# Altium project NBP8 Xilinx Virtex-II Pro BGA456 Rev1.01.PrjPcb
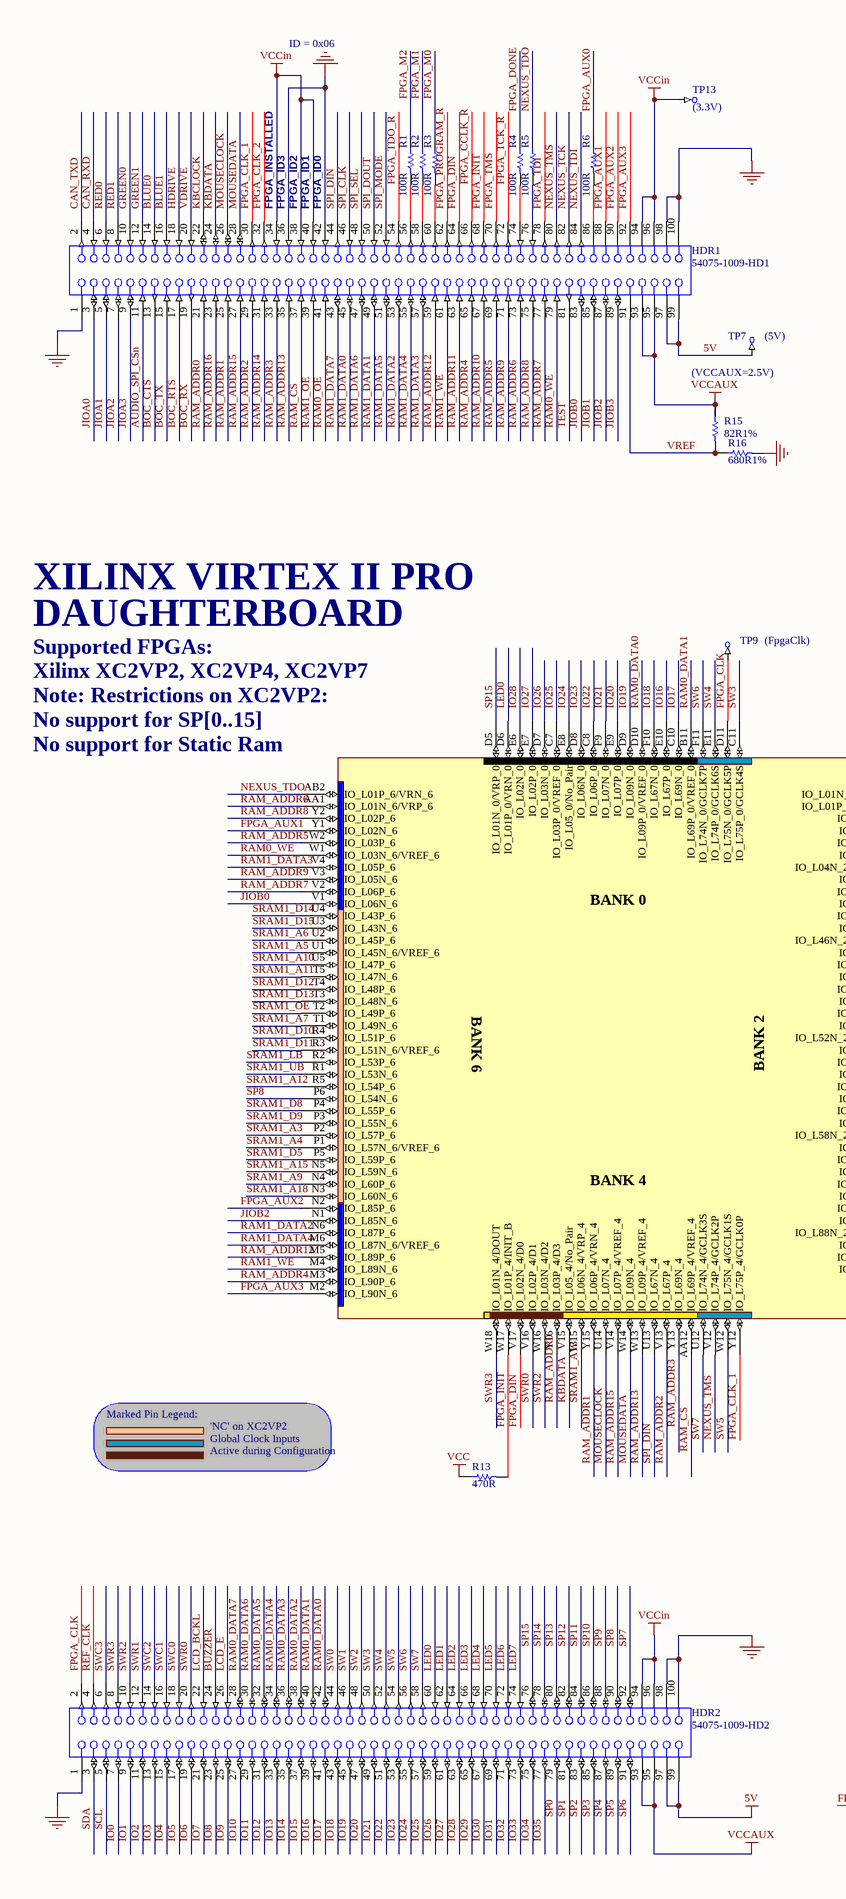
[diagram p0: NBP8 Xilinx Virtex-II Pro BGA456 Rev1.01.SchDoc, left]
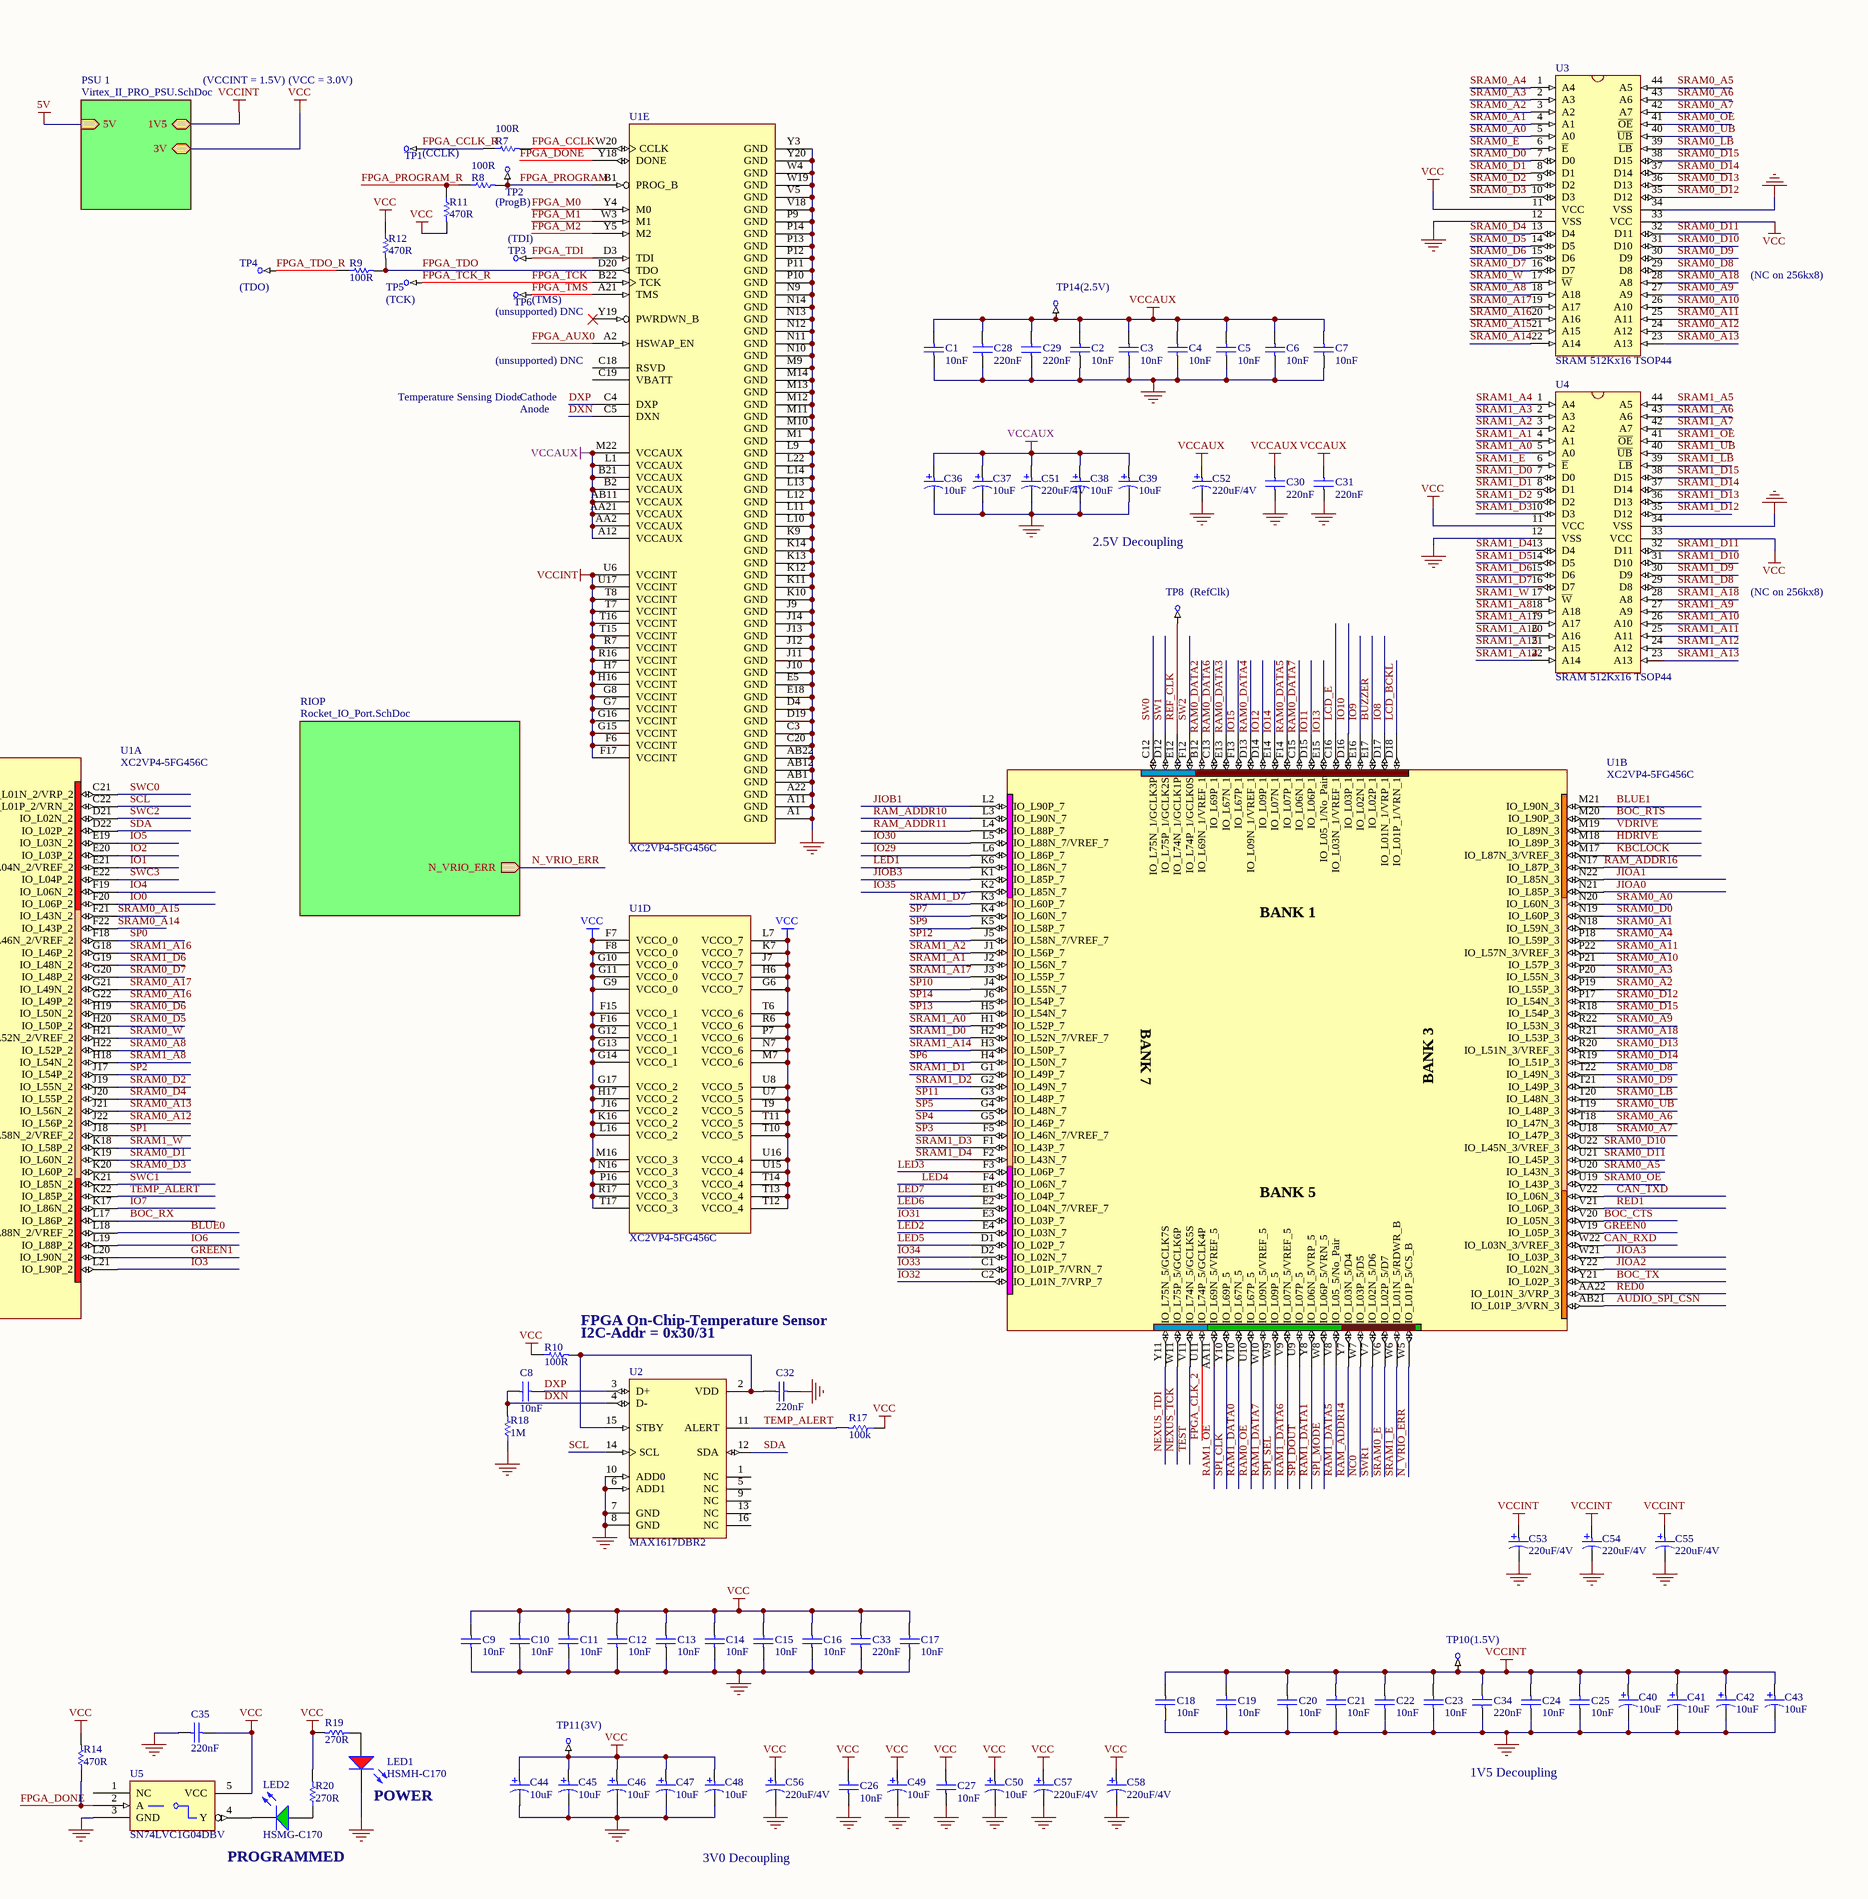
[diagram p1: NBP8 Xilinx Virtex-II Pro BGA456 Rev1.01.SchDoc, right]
3 sheets, 164 parts. Net scope: hierarchical (ports join the sheet entries above them; power ports are global).
Board file: NBP8 Xilinx Virtex-II Pro BGA456 Rev1.01.PcbDoc
Sheets:
  NBP8 Xilinx Virtex-II Pro BGA456 Rev1.01.SchDoc
    PSU 1 = Virtex_II_PRO_PSU.SchDoc
    RIOP = Rocket_IO_Port.SchDoc

## Sheet NBP8 Xilinx Virtex-II Pro BGA456 Rev1.01.SchDoc
size A2; Organization: Altium Limited; Address1: L3, 12a Rodborough Rd; Address2: Frenchs Forest; Address3: NSW; Address4: Australia 2086; DocumentNumber: 3; Revision: 1.01; SheetNumber: 3; SheetTotal: 3

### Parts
C1  10nF  [CC1608-0603]
C2  10nF  [CC1608-0603]
C3  10nF  [CC1608-0603]
C4  10nF  [CC1608-0603]
C5  10nF  [CC1608-0603]
C6  10nF  [CC1608-0603]
C7  10nF  [CC1608-0603]
C8  10nF  [CC1608-0603]
C9  10nF  [CC1608-0603]
C10  10nF  [CC1608-0603]
C11  10nF  [CC1608-0603]
C12  10nF  [CC1608-0603]
C13  10nF  [CC1608-0603]
C14  10nF  [CC1608-0603]
C15  10nF  [CC1608-0603]
C16  10nF  [CC1608-0603]
C17  10nF  [CC1608-0603]
C18  10nF  [CC1608-0603]
C19  10nF  [CC1608-0603]
C20  10nF  [CC1608-0603]
C21  10nF  [CC1608-0603]
C22  10nF  [CC1608-0603]
C23  10nF  [CC1608-0603]
C24  10nF  [CC1608-0603]
C25  10nF  [CC1608-0603]
C26  10nF  [CC1608-0603]
C27  10nF  [CC1608-0603]
C28  220nF  [CC1608-0603]
C29  220nF  [CC1608-0603]
C30  220nF  [CC1608-0603]
C31  220nF  [CC1608-0603]
C32  220nF  [CC1608-0603]
C33  220nF  [CC1608-0603]
C34  220nF  [CC1608-0603]
C35  220nF  [CC1608-0603]
C36  10uF  [MCCT-B]
C37  10uF  [MCCT-B]
C38  10uF  [MCCT-B]
C39  10uF  [MCCT-B]
C40  10uF  [MCCT-B]
C41  10uF  [MCCT-B]
C42  10uF  [MCCT-B]
C43  10uF  [MCCT-B]
C44  10uF  [MCCT-B]
C45  10uF  [MCCT-B]
C46  10uF  [MCCT-B]
C47  10uF  [MCCT-B]
C48  10uF  [MCCT-B]
C49  10uF  [MCCT-B]
C50  10uF  [MCCT-B]
C51  220uF/4V  [MCCT-D]
C52  220uF/4V  [MCCT-D]
C53  220uF/4V  [MCCT-D]
C54  220uF/4V  [MCCT-D]
C55  220uF/4V  [MCCT-D]
C56  220uF/4V  [MCCT-D]
C57  220uF/4V  [MCCT-D]
C58  220uF/4V  [MCCT-D]
HDR1  54075-1009-HD1  [54075]
HDR2  54075-1009-HD2  [54075]
LED1  HSMH-C170  [SMD _LED]
LED2  HSMG-C170  [SMD _LED]
R1  100R  [CC2012-0805]
R2  100R  [CC2012-0805]
R3  100R  [CC2012-0805]
R4  100R  [CC2012-0805]
R5  100R  [CC2012-0805]
R6  100R  [CC2012-0805]
R7  100R  [CC2012-0805]
R8  100R  [CC2012-0805]
R9  100R  [CC2012-0805]
R10  100R  [CC2012-0805]
R11  470R  [CC2012-0805]
R12  470R  [CC2012-0805]
R13  470R  [CC2012-0805]
R14  470R  [CC2012-0805]
R15  82R1%  [CC2012-0805]
R16  680R1%  [CC2012-0805]
R17  100k  [CC2012-0805]
R18  1M  [CC2012-0805]
R19  270R  [CC2012-0805]
R20  270R  [CC2012-0805]
TP1  (CCLK)  [TestPin]  (no BOM)
TP2  (ProgB)  [TestPin]  (no BOM)
TP3  (TDI)  [TestPin]  (no BOM)
TP4  (TDO)  [TestPin]  (no BOM)
TP5  (TCK)  [TestPin]  (no BOM)
TP6  (TMS)  [TestPin]  (no BOM)
TP7  (5V)  [TestPin]  (no BOM)
TP8  (RefClk)  [TestPin]  (no BOM)
TP9  (FpgaClk)  [TestPin]  (no BOM)
TP10  (1.5V)  [TestPin]  (no BOM)
TP11  (3V)  [TestPin]  (no BOM)
TP13  (3.3V)  [TestPin]  (no BOM)
TP14  (2.5V)  [TestPin]  (no BOM)
U1  XC2VP4-5FG456C  [FG456]  (parts A,B,D,E of 5)
U2  MAX1617DBR2  [QSOP16]
U3  SRAM 512Kx16 TSOP44  [SO-G44/P.8]
U4  SRAM 512Kx16 TSOP44  [SO-G44/P.8]
U5  SN74LVC1G04DBV  [SO-G5/P.95]

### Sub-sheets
PSU 1 = Virtex_II_PRO_PSU.SchDoc: 5V (in), 1V5, 3V
RIOP = Rocket_IO_Port.SchDoc: N_VRIO_ERR (out)

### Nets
5V: HDR1.97 HDR1.99 HDR2.97 HDR2.99 TP7.1 ; sheet PSU 1/5V
GND: C1.2 C2.2 C3.2 C4.2 C5.2 C6.2 C7.2 C9.2 C10.2 C11.2 C12.2 C13.2 C14.2 C15.2 C16.2 C17.2 C18.2 C19.2 C20.2 C21.2 C22.2 C23.2 C24.2 C25.2 C26.2 C27.2 C28.2 C29.2 C30.2 C31.2 C32.1 C33.2 C34.2 C35.2 C36.2 C37.2 C38.2 C39.2 C40.2 C41.2 C42.2 C43.2 C44.2 C45.2 C46.2 C47.2 C48.2 C49.2 C50.2 C51.2 C52.2 C53.2 C54.2 C55.2 C56.2 C57.2 C58.2 HDR1.1 HDR1.36 HDR1.42 HDR1.98 HDR1.100 HDR2.1 HDR2.98 HDR2.100 LED1.2(K) R16.2 R18.1 U1.A1(GND) U1.A11(GND) U1.A22(GND) U1.AB1(GND) U1.AB12(GND) U1.AB22(GND) U1.C3(GND) U1.C20(GND) U1.D4(GND) U1.D19(GND) U1.E5(GND) U1.E18(GND) U1.J9(GND) U1.J10(GND) U1.J11(GND) U1.J12(GND) U1.J13(GND) U1.J14(GND) U1.K9(GND) U1.K10(GND) U1.K11(GND) U1.K12(GND) U1.K13(GND) U1.K14(GND) U1.L9(GND) U1.L10(GND) U1.L11(GND) U1.L12(GND) U1.L13(GND) U1.L14(GND) U1.L22(GND) U1.M1(GND) U1.M9(GND) U1.M10(GND) U1.M11(GND) U1.M12(GND) U1.M13(GND) U1.M14(GND) U1.N9(GND) U1.N10(GND) U1.N11(GND) U1.N12(GND) U1.N13(GND) U1.N14(GND) U1.P9(GND) U1.P10(GND) U1.P11(GND) U1.P12(GND) U1.P13(GND) U1.P14(GND) U1.V5(GND) U1.V18(GND) U1.W4(GND) U1.W19(GND) U1.Y3(GND) U1.Y20(GND) U2.6(ADD1) U2.7(GND) U2.8(GND) U2.10(ADD0) U3.12(VSS) U3.34(VSS) U4.12(VSS) U4.34(VSS) U5.3(GND)
VCC: C9.1 C10.1 C11.1 C12.1 C13.1 C14.1 C15.1 C16.1 C17.1 C26.1 C27.1 C33.1 C35.1 C44.1 C45.1 C46.1 C47.1 C48.1 C49.1 C50.1 C56.1 C57.1 C58.1 R10.1 R11.2 R12.1 R13.1 R14.2 R17.1 R19.2 R20.2 TP11.1 U1.F7(VCCO_0) U1.F8(VCCO_0) U1.F15(VCCO_1) U1.F16(VCCO_1) U1.G6(VCCO_7) U1.G9(VCCO_0) U1.G10(VCCO_0) U1.G11(VCCO_0) U1.G12(VCCO_1) U1.G13(VCCO_1) U1.G14(VCCO_1) U1.G17(VCCO_2) U1.H6(VCCO_7) U1.H17(VCCO_2) U1.J7(VCCO_7) U1.J16(VCCO_2) U1.K7(VCCO_7) U1.K16(VCCO_2) U1.L7(VCCO_7) U1.L16(VCCO_2) U1.M7(VCCO_6) U1.M16(VCCO_3) U1.N7(VCCO_6) U1.N16(VCCO_3) U1.P7(VCCO_6) U1.P16(VCCO_3) U1.R6(VCCO_6) U1.R17(VCCO_3) U1.T6(VCCO_6) U1.T9(VCCO_5) U1.T10(VCCO_5) U1.T11(VCCO_5) U1.T12(VCCO_4) U1.T13(VCCO_4) U1.T14(VCCO_4) U1.T17(VCCO_3) U1.U7(VCCO_5) U1.U8(VCCO_5) U1.U15(VCCO_4) U1.U16(VCCO_4) U3.11(VCC) U3.33(VCC) U4.11(VCC) U4.33(VCC) U5.5(VCC) ; sheet PSU 1/3V
VCCAUX: C1.1 C2.1 C3.1 C4.1 C5.1 C6.1 C7.1 C28.1 C29.1 C30.1 C31.1 C36.1 C37.1 C38.1 C39.1 C51.1 C52.1 HDR1.93 HDR1.95 HDR2.93 HDR2.95 R15.1 TP14.1 U1.A12(VCCAUX) U1.AA2(VCCAUX) U1.AA21(VCCAUX) U1.AB11(VCCAUX) U1.B2(VCCAUX) U1.B21(VCCAUX) U1.L1(VCCAUX) U1.M22(VCCAUX)
VCCin: HDR1.34 HDR1.38 HDR1.40 HDR1.94 HDR1.96 HDR2.94 HDR2.96 TP13.1
VCCINT: C18.1 C19.1 C20.1 C21.1 C22.1 C23.1 C24.1 C25.1 C34.1 C40.1 C41.1 C42.1 C43.1 C53.1 C54.1 C55.1 TP10.1 U1.F6(VCCINT) U1.F17(VCCINT) U1.G7(VCCINT) U1.G8(VCCINT) U1.G15(VCCINT) U1.G16(VCCINT) U1.H7(VCCINT) U1.H16(VCCINT) U1.R7(VCCINT) U1.R16(VCCINT) U1.T7(VCCINT) U1.T8(VCCINT) U1.T15(VCCINT) U1.T16(VCCINT) U1.U6(VCCINT) U1.U17(VCCINT) ; sheet PSU 1/1V5
AUDIO_SPI_CSn: HDR1.11 U1.AB21(IO_L01P_3/VRN_3)
BLUE0: HDR1.14 U1.L18(IO_L88N_2/VREF_2)
BLUE1: HDR1.16 U1.M21(IO_L90N_3)
BOC_CTS: HDR1.13 U1.V20(IO_L05N_3)
BOC_RTS: HDR1.17 U1.M20(IO_L90P_3)
BOC_RX: HDR1.19 U1.L17(IO_L86P_2)
BOC_TX: HDR1.15 U1.Y21(IO_L02P_3)
BUZZER: HDR2.24 U1.E17(IO_L02P_1)
CAN_RXD: HDR1.4 U1.W22(IO_L03N_3/VREF_3)
CAN_TXD: HDR1.2 U1.V22(IO_L06N_3)
DXN: C8.1 R18.2 U1.C5(DXN) U2.4(D-)
DXP: C8.2 U1.C4(DXP) U2.3(D+)
FPGA_AUX0: R6.1 U1.A2(HSWAP_EN)
FPGA_AUX1: HDR1.88 U1.Y1(IO_L02N_6)
FPGA_AUX2: HDR1.90 U1.N2(IO_L85P_6)
FPGA_AUX3: HDR1.92 U1.M2(IO_L90N_6)
FPGA_CCLK: R7.2 U1.W20(CCLK)
FPGA_CCLK_R: HDR1.66 R7.1 TP1.1
FPGA_CLK: HDR2.2 TP9.1 U1.D11(IO_L75N_0/GCLK5P)
FPGA_CLK_1: HDR1.30 U1.Y12(IO_L75P_4/GCLK0P)
FPGA_CLK_2: HDR1.32 U1.U11(IO_L74P_5/GCLK4P)
FPGA_DIN: HDR1.64 U1.V17(IO_L02N_4/D0)
FPGA_DONE: R4.1 R14.1 U1.Y18(DONE) U5.2(A)
FPGA_INIT: HDR1.68 R13.2 U1.W17(IO_L01P_4/INIT_B)
FPGA_M0: R3.1 U1.Y4(M0)
FPGA_M1: R2.1 U1.W3(M1)
FPGA_M2: R1.1 U1.Y5(M2)
FPGA_PROGRAM: R8.2 TP2.1 U1.B1(PROG_B)
FPGA_PROGRAM_R: HDR1.62 R8.1 R11.1
FPGA_TCK: HDR1.72 TP5.1 U1.B22(TCK)  [also labelled FPGA_TCK_R]
FPGA_TDI: HDR1.78 TP3.1 U1.D3(TDI)
FPGA_TDO: R9.2 R12.2 U1.D20(TDO)
FPGA_TDO_R: HDR1.54 R9.1 TP4.1
FPGA_TMS: HDR1.70 TP6.1 U1.A21(TMS)
GREEN0: HDR1.10 U1.V19(IO_L05P_3)
GREEN1: HDR1.12 U1.L20(IO_L90N_2)
HDRIVE: HDR1.18 U1.M18(IO_L89P_3)
IO0: HDR2.7 U1.F20(IO_L06P_2)
IO1: HDR2.9 U1.E21(IO_L04N_2/VREF_2)
IO2: HDR2.11 U1.E20(IO_L03P_2)
IO3: HDR2.13 U1.L21(IO_L90P_2)
IO4: HDR2.15 U1.F19(IO_L06N_2)
IO5: HDR2.17 U1.E19(IO_L03N_2)
IO6: HDR2.19 U1.L19(IO_L88P_2)
IO7: HDR2.21 U1.K17(IO_L86N_2)
IO8: HDR2.23 U1.D17(IO_L01N_1/VRP_1)
IO9: HDR2.25 U1.E16(IO_L02N_1)
IO10: HDR2.27 U1.D16(IO_L03P_1)
IO11: HDR2.29 U1.D15(IO_L06P_1)
IO12: HDR2.31 U1.D14(IO_L09P_1)
IO13: HDR2.33 U1.E15(IO_L05_1/No_Pair)
IO14: HDR2.35 U1.E14(IO_L07N_1)
IO15: HDR2.37 U1.F13(IO_L67P_1)
IO16: HDR2.39 U1.E10(IO_L67P_0)
IO17: HDR2.41 U1.C10(IO_L69N_0)
IO18: HDR2.43 U1.F10(IO_L67N_0)
IO19: HDR2.45 U1.D9(IO_L09N_0)
IO20: HDR2.47 U1.E9(IO_L07P_0)
IO21: HDR2.49 U1.F9(IO_L07N_0)
IO22: HDR2.51 U1.C8(IO_L06P_0)
IO23: HDR2.53 U1.D8(IO_L06N_0)
IO24: HDR2.55 U1.E8(IO_L05_0/No_Pair)
IO25: HDR2.57 U1.C7(IO_L03P_0/VREF_0)
IO26: HDR2.59 U1.D7(IO_L03N_0)
IO27: HDR2.61 U1.E7(IO_L02P_0)
IO28: HDR2.63 U1.E6(IO_L02N_0)
IO29: HDR2.65 U1.L6(IO_L86P_7)
IO30: HDR2.67 U1.L5(IO_L88N_7/VREF_7)
IO31: HDR2.69 U1.E3(IO_L03P_7)
IO32: HDR2.71 U1.C2(IO_L01N_7/VRP_7)
IO33: HDR2.73 U1.C1(IO_L01P_7/VRN_7)
IO34: HDR2.75 U1.D2(IO_L02N_7)
IO35: HDR2.77 U1.K2(IO_L85N_7)
JIOA0: HDR1.3 U1.N21(IO_L85P_3)
JIOA1: HDR1.5 U1.N22(IO_L85N_3)
JIOA2: HDR1.7 U1.Y22(IO_L02N_3)
JIOA3: HDR1.9 U1.W21(IO_L03P_3)
JIOB0: HDR1.83 U1.V1(IO_L06N_6)
JIOB1: HDR1.85 U1.L2(IO_L90P_7)
JIOB2: HDR1.87 U1.N1(IO_L85N_6)
JIOB3: HDR1.89 U1.K1(IO_L85P_7)
KBCLOCK: HDR1.22 U1.M17(IO_L87N_3/VREF_3)
KBDATA: HDR1.24 U1.V15(IO_L05_4/No_Pair)
LCD_BCKL: HDR2.22 U1.D18(IO_L01P_1/VRN_1)
LCD_E: HDR2.26 U1.C16(IO_L03N_1/VREF_1)
LED0: HDR2.60 U1.D6(IO_L01P_0/VRN_0)
LED1: HDR2.62 U1.K6(IO_L86N_7)
LED2: HDR2.64 U1.E4(IO_L03N_7)
LED3: HDR2.66 U1.F3(IO_L06P_7)
LED4: HDR2.68 U1.F4(IO_L06N_7)
LED5: HDR2.70 U1.D1(IO_L02P_7)
LED6: HDR2.72 U1.E2(IO_L04N_7/VREF_7)
LED7: HDR2.74 U1.E1(IO_L04P_7)
MOUSECLOCK: HDR1.26 U1.U14(IO_L07N_4)
MOUSEDATA: HDR1.28 U1.W14(IO_L09N_4)
N_VRIO_ERR: U1.W5(IO_L01P_5/CS_B) ; sheet RIOP/N_VRIO_ERR
NC0: U1.W7(IO_L03P_5/D5)
NEXUS_TCK: HDR1.82 U1.W11(IO_L75P_5/GCLK6P)
NEXUS_TDI: HDR1.84 U1.Y11(IO_L75N_5/GCLK7S)
NEXUS_TDO: R5.1 U1.AB2(IO_L01P_6/VRN_6)
NEXUS_TMS: HDR1.80 U1.V12(IO_L74P_4/GCLK2P)
RAM0_DATA0: HDR2.42 U1.D10(IO_L09P_0/VREF_0)
RAM0_DATA1: HDR2.40 U1.B11(IO_L69P_0/VREF_0)
RAM0_DATA2: HDR2.38 U1.B12(IO_L69N_1/VREF_1)
RAM0_DATA3: HDR2.36 U1.E13(IO_L67N_1)
RAM0_DATA4: HDR2.34 U1.D13(IO_L09N_1/VREF_1)
RAM0_DATA5: HDR2.32 U1.F14(IO_L07P_1)
RAM0_DATA6: HDR2.30 U1.C13(IO_L69P_1)
RAM0_DATA7: HDR2.28 U1.C15(IO_L06N_1)
RAM0_OE: HDR1.41 U1.U10(IO_L67P_5)
RAM0_WE: HDR1.79 U1.W1(IO_L03N_6/VREF_6)
RAM1_DATA0: HDR1.45 U1.V10(IO_L67N_5)
RAM1_DATA1: HDR1.49 U1.Y8(IO_L06N_5/VRP_5)
RAM1_DATA2: HDR1.53 U1.N6(IO_L87P_6)
RAM1_DATA3: HDR1.57 U1.V4(IO_L05P_6)
RAM1_DATA4: HDR1.55 U1.M6(IO_L87N_6/VREF_6)
RAM1_DATA5: HDR1.51 U1.V8(IO_L05_5/No_Pair)
RAM1_DATA6: HDR1.47 U1.V9(IO_L07N_5/VREF_5)
RAM1_DATA7: HDR1.43 U1.W10(IO_L09N_5/VREF_5)
RAM1_OE: HDR1.39 U1.AA11(IO_L69N_5/VREF_5)
RAM1_WE: HDR1.61 U1.M4(IO_L89N_6)
RAM_ADDR0: HDR1.21 U1.Y16(IO_L03P_4/D3)
RAM_ADDR1: HDR1.25 U1.Y15(IO_L06P_4/VRN_4)
RAM_ADDR2: HDR1.29 U1.V13(IO_L67P_4)
RAM_ADDR3: HDR1.33 U1.Y13(IO_L69N_4)
RAM_ADDR4: HDR1.65 U1.M3(IO_L90P_6)
RAM_ADDR5: HDR1.69 U1.W2(IO_L03P_6)
RAM_ADDR6: HDR1.73 U1.AA1(IO_L01N_6/VRP_6)
RAM_ADDR7: HDR1.77 U1.V2(IO_L06P_6)
RAM_ADDR8: HDR1.75 U1.Y2(IO_L02P_6)
RAM_ADDR9: HDR1.71 U1.V3(IO_L05N_6)
RAM_ADDR10: HDR1.67 U1.L3(IO_L90N_7)
RAM_ADDR11: HDR1.63 U1.L4(IO_L88P_7)
RAM_ADDR12: HDR1.59 U1.M5(IO_L89P_6)
RAM_ADDR13: HDR1.35 U1.W13(IO_L09P_4/VREF_4)
RAM_ADDR14: HDR1.31 U1.Y7(IO_L03N_5/D4)
RAM_ADDR15: HDR1.27 U1.V14(IO_L07P_4/VREF_4)
RAM_ADDR16: HDR1.23 U1.N17(IO_L87P_3)
RAM_CS: HDR1.37 U1.AA12(IO_L69P_4/VREF_4)
RED0: HDR1.6 U1.AA22(IO_L01N_3/VRP_3)
RED1: HDR1.8 U1.V21(IO_L06P_3)
REF_CLK: HDR2.4 TP8.1 U1.E12(IO_L74N_1/GCLK1P)
SCL: HDR2.5 U1.C22(IO_L01P_2/VRN_2) U2.14(SCL)
SDA: HDR2.3 U1.D22(IO_L02P_2) U2.12(SDA)
SP0: HDR2.79 U1.F18(IO_L46N_2/VREF_2)
SP1: HDR2.81 U1.J18(IO_L58N_2/VREF_2)
SP2: HDR2.83 U1.J17(IO_L54P_2)
SP3: HDR2.85 U1.F5(IO_L46N_7/VREF_7)
SP4: HDR2.87 U1.G5(IO_L46P_7)
SP5: HDR2.89 U1.G4(IO_L48N_7)
SP6: HDR2.91 U1.H4(IO_L50N_7)
SP7: HDR2.92 U1.K4(IO_L60N_7)
SP8: HDR2.90 U1.P6(IO_L54N_6)
SP9: HDR2.88 U1.K5(IO_L58P_7)
SP10: HDR2.86 U1.J4(IO_L55N_7)
SP11: HDR2.84 U1.G3(IO_L48P_7)
SP12: HDR2.82 U1.J5(IO_L58N_7/VREF_7)
SP13: HDR2.80 U1.H5(IO_L54N_7)
SP14: HDR2.78 U1.J6(IO_L54P_7)
SP15: HDR2.76 U1.D5(IO_L01N_0/VRP_0)
SPI_CLK: HDR1.46 U1.Y10(IO_L69P_5)
SPI_DIN: HDR1.44 U1.U13(IO_L67N_4)
SPI_DOUT: HDR1.50 U1.U9(IO_L07P_5)
SPI_MODE: HDR1.52 U1.W8(IO_L06P_5/VRN_5)
SPI_SEL: HDR1.48 U1.W9(IO_L09P_5)
SRAM0_A0: U1.N20(IO_L60N_3) U3.5(A0)
SRAM0_A1: U1.N18(IO_L59N_3) U3.4(A1)
SRAM0_A2: U1.P19(IO_L55P_3) U3.3(A2)
SRAM0_A3: U1.P20(IO_L55N_3) U3.2(A3)
SRAM0_A4: U1.P18(IO_L59P_3) U3.1(A4)
SRAM0_A5: U1.U20(IO_L43N_3) U3.44(A5)
SRAM0_A6: U1.T18(IO_L47N_3) U3.43(A6)
SRAM0_A7: U1.U18(IO_L47P_3) U3.42(A7)
SRAM0_A8: U1.H22(IO_L52P_2) U3.18(A18)
SRAM0_A9: U1.R22(IO_L53N_3) U3.27(A9)
SRAM0_A10: U1.P21(IO_L57P_3) U3.26(A10)
SRAM0_A11: U1.P22(IO_L57N_3/VREF_3) U3.25(A11)
SRAM0_A12: U1.J22(IO_L56P_2) U3.24(A12)
SRAM0_A13: U1.J21(IO_L56N_2) U3.23(A13)
SRAM0_A14: U1.F22(IO_L43P_2) U3.22(A14)
SRAM0_A15: U1.F21(IO_L43N_2) U3.21(A15)
SRAM0_A16: U1.G22(IO_L49P_2) U3.20(A16)
SRAM0_A17: U1.G21(IO_L49N_2) U3.19(A17)
SRAM0_A18: U1.R21(IO_L53P_3) U3.28(A8)
SRAM0_D0: U1.N19(IO_L60P_3) U3.7(D0)
SRAM0_D1: U1.K19(IO_L60N_2) U3.8(D1)
SRAM0_D2: U1.J19(IO_L55N_2) U3.9(D2)
SRAM0_D3: U1.K20(IO_L60P_2) U3.10(D3)
SRAM0_D4: U1.J20(IO_L55P_2) U3.13(D4)
SRAM0_D5: U1.H20(IO_L50P_2) U3.14(D5)
SRAM0_D6: U1.H19(IO_L50N_2) U3.15(D6)
SRAM0_D7: U1.G20(IO_L48P_2) U3.16(D7)
SRAM0_D8: U1.T22(IO_L49N_3) U3.29(D8)
SRAM0_D9: U1.T21(IO_L49P_3) U3.30(D9)
SRAM0_D10: U1.U22(IO_L45N_3/VREF_3) U3.31(D10)
SRAM0_D11: U1.U21(IO_L45P_3) U3.32(D11)
SRAM0_D12: U1.P17(IO_L54N_3) U3.35(D12)
SRAM0_D13: U1.R20(IO_L51N_3/VREF_3) U3.36(D13)
SRAM0_D14: U1.R19(IO_L51P_3) U3.37(D14)
SRAM0_D15: U1.R18(IO_L54P_3) U3.38(D15)
SRAM0_E: U1.V6(IO_L02P_5/D7) U3.6(~{E})
SRAM0_LB: U1.T20(IO_L48N_3) U3.39(~{LB})
SRAM0_OE: U1.U19(IO_L43P_3) U3.41(~{OE})
SRAM0_UB: U1.T19(IO_L48P_3) U3.40(~{UB})
SRAM0_W: U1.H21(IO_L52N_2/VREF_2) U3.17(~{W})
SRAM1_A0: U1.H1(IO_L52P_7) U4.5(A0)
SRAM1_A1: U1.J2(IO_L56N_7) U4.4(A1)
SRAM1_A2: U1.J1(IO_L56P_7) U4.3(A2)
SRAM1_A3: U1.P2(IO_L57P_6) U4.2(A3)
SRAM1_A4: U1.P1(IO_L57N_6/VREF_6) U4.1(A4)
SRAM1_A5: U1.U1(IO_L45N_6/VREF_6) U4.44(A5)
SRAM1_A6: U1.U2(IO_L45P_6) U4.43(A6)
SRAM1_A7: U1.T1(IO_L49N_6) U4.42(A7)
SRAM1_A8: U1.H18(IO_L54N_2) U4.18(A18)
SRAM1_A9: U1.N4(IO_L60P_6) U4.27(A9)
SRAM1_A10: U1.U5(IO_L47P_6) U4.26(A10)
SRAM1_A11: U1.T5(IO_L47N_6) U4.25(A11)
SRAM1_A12: U1.R5(IO_L54P_6) U4.24(A12)
SRAM1_A13: U1.W15(IO_L06N_4/VRP_4) U4.23(A13)
SRAM1_A14: U1.H3(IO_L50P_7) U4.22(A14)
SRAM1_A15: U1.N5(IO_L59N_6) U4.21(A15)
SRAM1_A16: U1.G18(IO_L46P_2) U4.20(A16)
SRAM1_A17: U1.J3(IO_L55P_7) U4.19(A17)
SRAM1_A18: U1.N3(IO_L60N_6) U4.28(A8)
SRAM1_D0: U1.H2(IO_L52N_7/VREF_7) U4.7(D0)
SRAM1_D1: U1.G1(IO_L49P_7) U4.8(D1)
SRAM1_D2: U1.G2(IO_L49N_7) U4.9(D2)
SRAM1_D3: U1.F1(IO_L43P_7) U4.10(D3)
SRAM1_D4: U1.F2(IO_L43N_7) U4.13(D4)
SRAM1_D5: U1.P5(IO_L59P_6) U4.14(D5)
SRAM1_D6: U1.G19(IO_L48N_2) U4.15(D6)
SRAM1_D7: U1.K3(IO_L60P_7) U4.16(D7)
SRAM1_D8: U1.P4(IO_L55P_6) U4.29(D8)
SRAM1_D9: U1.P3(IO_L55N_6) U4.30(D9)
SRAM1_D10: U1.R4(IO_L51P_6) U4.31(D10)
SRAM1_D11: U1.R3(IO_L51N_6/VREF_6) U4.32(D11)
SRAM1_D12: U1.T4(IO_L48P_6) U4.35(D12)
SRAM1_D13: U1.T3(IO_L48N_6) U4.36(D13)
SRAM1_D14: U1.U4(IO_L43P_6) U4.37(D14)
SRAM1_D15: U1.U3(IO_L43N_6) U4.38(D15)
SRAM1_E: U1.W6(IO_L01N_5/RDWR_B) U4.6(~{E})
SRAM1_LB: U1.R2(IO_L53P_6) U4.39(~{LB})
SRAM1_OE: U1.T2(IO_L49P_6) U4.41(~{OE})
SRAM1_UB: U1.R1(IO_L53N_6) U4.40(~{UB})
SRAM1_W: U1.K18(IO_L58P_2) U4.17(~{W})
SW0: HDR2.44 U1.C12(IO_L75N_1/GCLK3P)
SW1: HDR2.46 U1.D12(IO_L75P_1/GCLK2S)
SW2: HDR2.48 U1.F12(IO_L74P_1/GCLK0S)
SW3: HDR2.50 U1.C11(IO_L75P_0/GCLK4S)
SW4: HDR2.52 U1.E11(IO_L74P_0/GCLK6S)
SW5: HDR2.54 U1.W12(IO_L75N_4/GCLK1S)
SW6: HDR2.56 U1.F11(IO_L74N_0/GCLK7P)
SW7: HDR2.58 U1.U12(IO_L74N_4/GCLK3S)
SWC0: HDR2.18 U1.C21(IO_L01N_2/VRP_2)
SWC1: HDR2.16 U1.K21(IO_L85N_2)
SWC2: HDR2.14 U1.D21(IO_L02N_2)
SWC3: HDR2.6 U1.E22(IO_L04P_2)
SWR0: HDR2.20 U1.V16(IO_L02P_4/D1)
SWR1: HDR2.12 U1.V7(IO_L02N_5/D6)
SWR2: HDR2.10 U1.W16(IO_L03N_4/D2)
SWR3: HDR2.8 U1.W18(IO_L01N_4/DOUT)
TEMP_ALERT: R17.2 U1.K22(IO_L85P_2) U2.11(ALERT)
TEST: HDR1.81 U1.V11(IO_L74N_5/GCLK5S)
VDRIVE: HDR1.20 U1.M19(IO_L89N_3)
VREF: HDR1.91 R15.2 R16.1
NetC32_2: C32.2 R10.2 U2.2(VDD) U2.15(STBY)
NetHDR1_56: HDR1.56 R1.2
NetHDR1_58: HDR1.58 R2.2
NetHDR1_60: HDR1.60 R3.2
NetHDR1_74: HDR1.74 R4.2
NetHDR1_76: HDR1.76 R5.2
NetHDR1_86: HDR1.86 R6.2
NetLED1_1: LED1.1(A) R19.1
NetLED2_1: LED2.1(A) R20.1
NetLED2_2: LED2.2(K) U5.4(Y)

Not connected (* = marked no-connect by the designer): U1 C18(RSVD) C19(VBATT) Y19(PWRDWN_B)*; U2 1(NC) 5(NC) 9(NC) 13(NC) 16(NC); U5 1(NC)

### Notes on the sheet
- ID = 0x06
- (VCCINT = 1.5V)
- (VCC = 3.0V)
- (near HDR1) FPGA_INSTALLED
- (near HDR1) FPGA_ID3
- (near HDR1) FPGA_ID2
- (near HDR1) FPGA_ID1
- (near HDR1) FPGA_ID0
- (NC on 256kx8)
- (near TP6) (unsupported) DNC
- (VCCAUX=2.5V)
- Temperature Sensing Diode
- (unsupported) DNC
- Anode
- Cathode
- XILINX VIRTEX II PRO
- 2.5V Decoupling
- DAUGHTERBOARD
- Supported FPGAs:
- Xilinx XC2VP2, XC2VP4, XC2VP7
- Note: Restrictions on XC2VP2:
- (near U1) No support for SP[0..15]
- (near U1) No support for Static Ram
- (near R10) FPGA On-Chip-Temperature Sensor
- (near R10) I2C-Addr = 0x30/31
- Marked Pin Legend:
- 'NC' on XC2VP2
- Global Clock Inputs
- Active during Configuration
- (near LED1) POWER
- 1V5 Decoupling
- PROGRAMMED
- 3V0 Decoupling

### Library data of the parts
C1-C35 = CAP: Capacitor
C36-C58 = CAP_POLAR: Polar Capacitor
HDR1 = 54075-1009-HD1: Board-to-Board, Docking Station, 0.80mm (.031") Pitch, Shielded Receptacle, Vertical, Ultra Low Profile, SMT; Manufacturer: Molex; Package Information: Latest Revision: Jun-2001; Mating Height: 8.5mm; Voltage: 100V; Current: 0.5A; Contact Resistance: 40mOhm max; PCB Layout: Complies with Manufacturer's Recommendation.
HDR2 = 54075-1009-HD2: Board-to-Board, Docking Station, 0.80mm (.031") Pitch, Shielded Receptacle, Vertical, Ultra Low Profile, SMT; Manufacturer: Molex; Package Information: Latest Revision: Jun-2001; Mating Height: 8.5mm; Voltage: 100V; Current: 0.5A; Contact Resistance: 40mOhm max; PCB Layout: Complies with Manufacturer's Recommendation.
LED1 = HSMX-C670: Typical RED GaAs SMD LED Agilent make; Manufacturer: Generic Components; Class I: Optoelectronic; Fitted: True
LED2 = HSMX-C670: Typical GREEN GaAs SMD LED Agilent make; Manufacturer: Generic Components; Class I: Optoelectronic; Fitted: True
R1-R20 = RES: Resistor
TP1-TP11 TP13 TP14 = TestPin
U1 = XC2VP4-5FG456C: Virtex-II Pro Platform FPGA, 456-Ball FBGA, Speed Grade 5, 248 User I/Os, Commercial Grade; Manufacturer Recommendation: Solder pad diameter 0.45mm SMD; Package Information: Latest Revision: ver1.1, Apr-2001; User I/Os: 248 Available; Code - JEDEC: MO-151-AAJ-1
U2 = MAX1617DBR2: SMBus Temperature Sensor with Internal and External Diode Input; Package Information: Latest Revision: Feb-2000
U3 U4 = SRAM 512Kx16 TSOP44: 512Kx16Bit SRAM TSOP44
U5 = SN74AHC1G04DBVR: Manufacturer: TI; Fitted: True

## Sheet Virtex_II_PRO_PSU.SchDoc
size A4; DocumentNumber: 1; Revision: 1.01; SheetNumber: 1; SheetTotal: 3
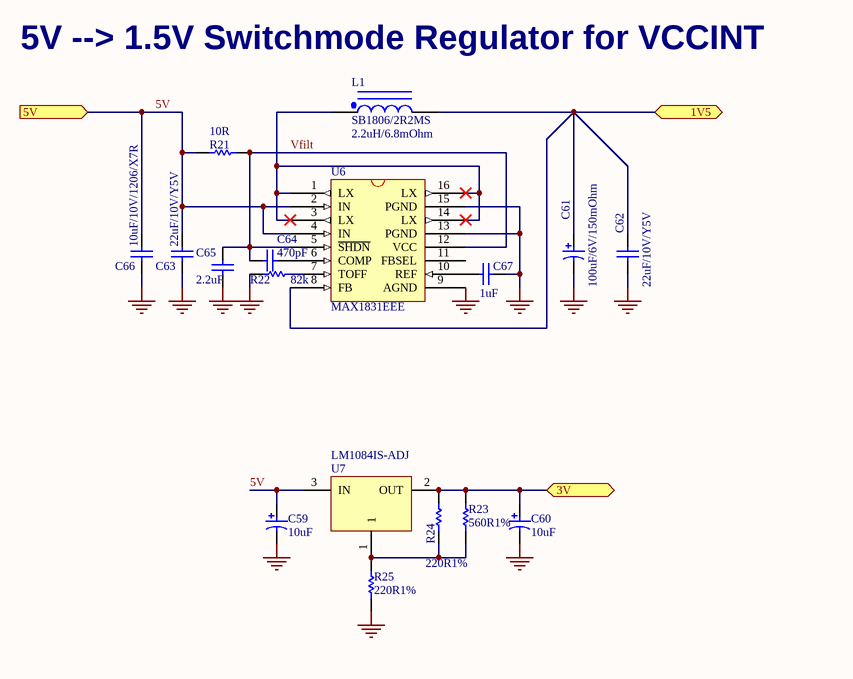
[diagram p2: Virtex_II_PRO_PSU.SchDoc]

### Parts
C59  10uF  [MCCT-B]
C60  10uF  [MCCT-B]
C61  100uF/6V/150mOhm  [MCCT-D]
C62  22uF/10V/Y5V  [CC3225-1210]
C63  22uF/10V/Y5V  [CC3225-1210]
C64  470pF  [CC1608-0603]
C65  2.2uF  [CC3216-1206]
C66  10uF/10V/1206/X7R  [CC3216-1206]
C67  1uF  [CC3216-1206]
L1  SB1806/2R2MS  value 2.2uH/6.8mOhm  [IND SB1806]
R21  10R  [CC2012-0805]
R22  82k  [CC2012-0805]
R23  560R1%  [CC2012-0805]
R24  220R1%  [CC2012-0805]
R25  220R1%  [CC2012-0805]
U6  MAX1831EEE  [QSOP16_150_25]
U7  LM1084IS-ADJ  [TO-263]

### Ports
1V5, 3V, 5V (in)

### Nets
5V: C59.1 C63.2 C66.2 R21.2 U6.2(IN) U6.4(IN) U7.3(IN) ; port 5V
GND: C59.2 C60.2 C61.2 C62.1 C63.1 C65.1 C66.1 C67.2 R22.1 R25.2 U6.9(AGND) U6.13(PGND) U6.15(PGND)
VCC: C60.1 R23.1 R24.1 U7.2(OUT) ; port 3V
VCCINT: C61.1 C62.2 L1.2 U6.8(FB) ; port 1V5
Vfilt: C64.1 C65.2 R21.1 U6.5(~{SHDN}) U6.12(VCC)
NetC64_2: C64.2 U6.6(COMP)
NetC67_1: C67.1 U6.10(REF)
NetL1_1: L1.1 U6.1(LX) U6.3(LX) U6.14(LX) U6.16(LX)
NetR22_2: R22.2 U6.7(TOFF)
NetR23_2: R23.2 R24.2 R25.1 U7.1

Not connected (* = marked no-connect by the designer): U6 11(FBSEL)

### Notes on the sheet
- 5V --> 1.5V Switchmode Regulator for VCCINT

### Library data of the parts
C59-C61 = CAP_POLAR: Polar Capacitor
C62-C67 = CAP: Capacitor
L1 = Inductor Iron Dot: Magnetic-Core Inductor with Winding Polarity Marking
R21-R25 = RES: Resistor
U6 = MAX1831EEE: 3A,!MHz, Low Voltage, Step-Down Regulator with Synchronous Rectification and Internal Switches
U7 = LM1084IS-ADJ: 5A Low Dropout Positive Regulators; Manufacturer: National Semi

## Sheet Rocket_IO_Port.SchDoc
size A4; Organization: Altium Limited; Address1: L3, 12a Rodborough Rd; Address2: Frenchs Forest; Address3: NSW; Address4: Australia 2086; DocumentNumber: 2; Revision: 1.01; SheetNumber: 2; SheetTotal: 3
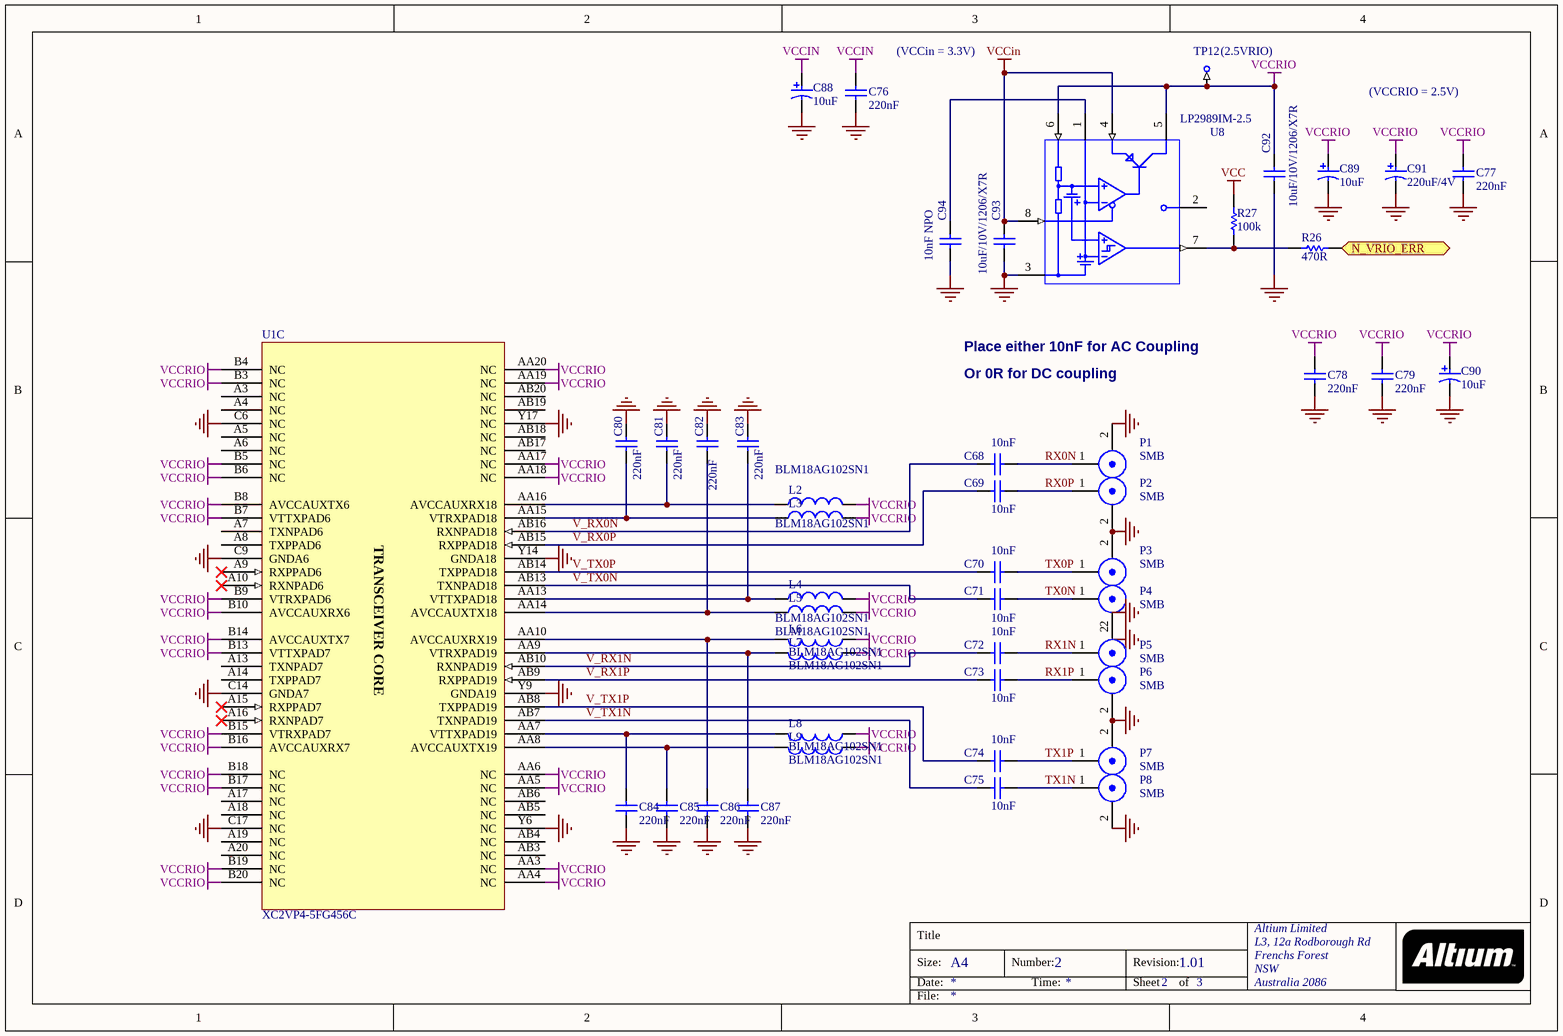
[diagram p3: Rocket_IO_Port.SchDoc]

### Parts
C68  10nF  [CC1005-0402]
C69  10nF  [CC1005-0402]
C70  10nF  [CC1005-0402]
C71  10nF  [CC1005-0402]
C72  10nF  [CC1005-0402]
C73  10nF  [CC1005-0402]
C74  10nF  [CC1005-0402]
C75  10nF  [CC1005-0402]
C76  220nF  [CC1608-0603]
C77  220nF  [CC1608-0603]
C78  220nF  [CC1608-0603]
C79  220nF  [CC1608-0603]
C80  220nF  [CC1608-0603]
C81  220nF  [CC1608-0603]
C82  220nF  [CC1608-0603]
C83  220nF  [CC1608-0603]
C84  220nF  [CC1608-0603]
C85  220nF  [CC1608-0603]
C86  220nF  [CC1608-0603]
C87  220nF  [CC1608-0603]
C88  10uF  [MCCT-B]
C89  10uF  [MCCT-B]
C90  10uF  [MCCT-B]
C91  220uF/4V  [MCCT-D]
C92  10uF/10V/1206/X7R  [CC3216-1206]
C93  10uF/10V/1206/X7R  [CC3216-1206]
C94  10nF NPO  [CC3216-1206]
L2  value BLM18AG102SN1  [CC1608-0603]  (hidden comment: Inductor)
L3  value BLM18AG102SN1  [CC1608-0603]  (hidden comment: Inductor)
L4  value BLM18AG102SN1  [CC1608-0603]  (hidden comment: Inductor)
L5  value BLM18AG102SN1  [CC1608-0603]  (hidden comment: Inductor)
L6  value BLM18AG102SN1  [CC1608-0603]  (hidden comment: Inductor)
L7  value BLM18AG102SN1  [CC1608-0603]  (hidden comment: Inductor)
L8  value BLM18AG102SN1  [CC1608-0603]  (hidden comment: Inductor)
L9  value BLM18AG102SN1  [CC1608-0603]  (hidden comment: Inductor)
P1  SMB  [SMB_V-RJ45]
P2  SMB  [SMB_V-RJ45]
P3  SMB  [SMB_V-RJ45]
P4  SMB  [SMB_V-RJ45]
P5  SMB  [SMB_V-RJ45]
P6  SMB  [SMB_V-RJ45]
P7  SMB  [SMB_V-RJ45]
P8  SMB  [SMB_V-RJ45]
R26  470R  [CC2012-0805]
R27  100k  [CC2012-0805]
TP12  (2.5VRIO)  [TestPin]  (no BOM)
U1  XC2VP4-5FG456C  [FG456]  (part C of 5)
U8  LP2989IM-2.5  [SO-8]

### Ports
N_VRIO_ERR (out)

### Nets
GND: C76.2 C77.2 C78.2 C79.2 C80.1 C81.1 C82.1 C83.1 C84.1 C85.1 C86.1 C87.1 C88.2 C89.2 C90.2 C91.2 C92.1 C93.1 C94.2 P1.2(Y) P2.2(Y) P3.2(Y) P4.2(Y) P5.2(Y) P6.2(Y) P7.2(Y) P8.2(Y) U1.C6(NC) U1.C9(GNDA6) U1.C14(GNDA7) U1.C17(NC) U1.Y6(NC) U1.Y9(GNDA19) U1.Y14(GNDA18) U1.Y17(NC) U8.3(GND)
VCC: R27.2
VCCin: C76.1 C88.1 C93.2 U8.4(INPUT) U8.8(S~{/}/D/)
VCCRIO: C77.1 C78.1 C79.1 C89.1 C90.1 C91.1 C92.2 L2.2 L3.2 L4.2 L5.2 L6.2 L7.2 L8.2 L9.2 TP12.1 U1.AA3(NC) U1.AA4(NC) U1.AA5(NC) U1.AA6(NC) U1.AA17(NC) U1.AA18(NC) U1.AA19(NC) U1.AA20(NC) U1.B3(NC) U1.B4(NC) U1.B5(NC) U1.B6(NC) U1.B7(VTTXPAD6) U1.B8(AVCCAUXTX6) U1.B9(VTRXPAD6) U1.B10(AVCCAUXRX6) U1.B13(VTTXPAD7) U1.B14(AVCCAUXTX7) U1.B15(VTRXPAD7) U1.B16(AVCCAUXRX7) U1.B17(NC) U1.B18(NC) U1.B19(NC) U1.B20(NC) U8.5(OUTPUT) U8.6(SENSE)
N_VRIO_ERR: R26.2 ; port N_VRIO_ERR
RX0N: C68.2 P1.1(X)
RX0P: C69.2 P2.1(X)
RX1N: C72.2 P5.1(X)
RX1P: C73.2 P6.1(X)
TX0N: C71.2 P4.1(X)
TX0P: C70.2 P3.1(X)
TX1N: C75.2 P8.1(X)
TX1P: C74.2 P7.1(X)
V_RX0N: C68.1 U1.AB16(RXNPAD18)
V_RX0P: C69.1 U1.AB15(RXPPAD18)
V_RX1N: C72.1 U1.AB10(RXNPAD19)
V_RX1P: C73.1 U1.AB9(RXPPAD19)
V_TX0N: C71.1 U1.AB13(TXNPAD18)
V_TX0P: C70.1 U1.AB14(TXPPAD18)
V_TX1N: C75.1 U1.AB7(TXNPAD19)
V_TX1P: C74.1 U1.AB8(TXPPAD19)
NetC80_2: C80.2 L3.1 U1.AA15(VTRXPAD18)
NetC81_2: C81.2 L2.1 U1.AA16(AVCCAUXRX18)
NetC82_2: C82.2 L5.1 U1.AA14(AVCCAUXTX18)
NetC83_2: C83.2 L4.1 U1.AA13(VTTXPAD18)
NetC84_2: C84.2 L8.1 U1.AA7(VTTXPAD19)
NetC85_2: C85.2 L9.1 U1.AA8(AVCCAUXTX19)
NetC86_2: C86.2 L6.1 U1.AA10(AVCCAUXRX19)
NetC87_2: C87.2 L7.1 U1.AA9(VTRXPAD19)
NetC94_1: C94.1 U8.1(BYPASS)
NetR26_1: R26.1 R27.1 U8.7(~{ERROR})

Not connected (* = marked no-connect by the designer): U1 A3(NC) A4(NC) A5(NC) A6(NC) A7(TXNPAD6) A8(TXPPAD6) A9(RXPPAD6)* A10(RXNPAD6)* A13(TXNPAD7) A14(TXPPAD7) A15(RXPPAD7)* A16(RXNPAD7)* A17(NC) A18(NC) A19(NC) A20(NC) AB3(NC) AB4(NC) AB5(NC) AB6(NC) AB17(NC) AB18(NC) AB19(NC) AB20(NC); U8 2(N/C)

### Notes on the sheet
- (near C76) (VCCin = 3.3V)
- (VCCRIO = 2.5V)
- Place either 10nF for AC Coupling
- Or 0R for DC coupling

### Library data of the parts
C68-C87 C92-C94 = CAP: Capacitor
C88-C91 = CAP_POLAR: Polar Capacitor
P1-P8 = SMB: SMB Straight Connector
R26 R27 = RES: Resistor
TP12 = TestPin
U1 = XC2VP4-5FG456C: as U1 on sheet NBP8 Xilinx Virtex-II Pro BGA456 Rev1.01
U8 = LP2989: NS Micropower/Low Noise 500mA LDO

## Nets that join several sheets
5V: NBP8 Xilinx Virtex-II Pro BGA456 Rev1.01 (5 pins), Virtex_II_PRO_PSU (7 pins)
GND: NBP8 Xilinx Virtex-II Pro BGA456 Rev1.01 (133 pins), Virtex_II_PRO_PSU (13 pins), Rocket_IO_Port (36 pins)
VCC: NBP8 Xilinx Virtex-II Pro BGA456 Rev1.01 (77 pins), Virtex_II_PRO_PSU (C60.1 R23.1 R24.1 U7.2), Rocket_IO_Port (R27.2)
VCCin: NBP8 Xilinx Virtex-II Pro BGA456 Rev1.01 (8 pins), Rocket_IO_Port (5 pins)
VCCINT: NBP8 Xilinx Virtex-II Pro BGA456 Rev1.01 (33 pins), Virtex_II_PRO_PSU (C61.1 C62.2 L1.2 U6.8)
N_VRIO_ERR: NBP8 Xilinx Virtex-II Pro BGA456 Rev1.01 (U1.W5), Rocket_IO_Port (R26.2)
